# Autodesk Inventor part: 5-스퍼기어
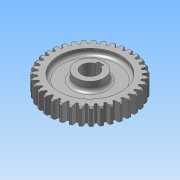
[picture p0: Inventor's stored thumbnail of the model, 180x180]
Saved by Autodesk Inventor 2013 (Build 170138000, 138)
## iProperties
Created: 2013-08
Part Number: 5-스퍼기어
Material: 강
Document SubType Name: Modeling
Designer: 한국산업디자인학원
Categories: <?xml version="1.0" encoding="UTF-16"?> <MemberInstance><Categories><FamilyTemplate><FamilyTemplateParameter ValueType="xs:double" Id="1" ObjectReferenceKey="da
Density: 1 g/cm^3
CustomPartVersion: 1
Author: 한국산업디자인학원
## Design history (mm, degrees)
sketch "Sketch1"
  geometry: C1 r 37 at (0, 0)
  constraints: 1 centre point
  dimensions: "d0" = 74 diameter of C1 (= da_da)
extrude "Extrusion1" new body sketch "Sketch1" distance "d1" = 15 (= da_b); taper "d2" = 0 deg
chamfer "모따기1" distance "d49" = 1; stored, may be unused: second distance "d50" = 2, angle "d51" = 45 deg
workplane "Work Plane2"
feature "피치 지름" dims "d4" = 10, "d5" = 0
workplane "Work Plane8"
workplane "Work Plane9"
feature "스퍼 기어" dims "da_b" = 15, "da_d" = 70, "da_aw" = 70, "da_da" = 74, "da_df" = 65, "da_dw" = 70, angle "da_beta" = 0 deg, "da_lefttooth" = 0, "da_righttooth" = 0
node "작업 평면11"
sketch "스케치3"
  geometry: C1 r 12.5 at (0, 0); 1 further point
  constraints: 1 centre point, 1 coincident
  dimensions: "d53" = 25 diameter of C1
extrude "돌출2" join sketch "스케치3" distance "d55" = 31; taper "d56" = 0 deg
sketch "스케치4"
  geometry: L1 (-2.5, 7.071)-(-2.5, 9.8); L2 (-2.5, 9.8)-(2.5, 9.8); L3 (2.5, 9.8)-(2.5, 7.071); C1 r 12.5 at (0, 0) reference; A1 r 7.5 centre (0, 0) between (-2.5, 7.071) and (2.5, 7.071); 1 further point
  constraints: 6 end point, 2 parallel, 2 point on circle, 1 centre point, 1 coincident, 1 midpoint, 1 perpendicular, 1 vertical, 1 vertical alignment
  dimensions: "d57" = 15 diameter of A1; "d59" = 5 distance of L1.end L2.end; "d60" = 17.3 dimension on A1 L2
extrude "돌출3" cut sketch "스케치4" stored distance "d61" = 31; taper "d62" = 0 deg
sketch "스케치5"
  geometry: C1 r 12.5 at (0, 0) reference; C2 r 27.5 at (0, 0); A1 r 36 centre (0, 0) between (-5.215, 35.62) and (-7.633, 35.181) reference
  constraints: 1 centre point, 1 coincident
  dimensions: "d63" = 55 diameter of C2
extrude "돌출4" cut sketch "스케치5" distance "d65" = 5; taper "d66" = 0 deg
sketch "스케치6"
  geometry: C1 r 12.5 at (0, 0) reference; C2 r 27.5 at (0, 0); A1 r 32.5 centre (0, 0) between (9.347, 31.127) and (7.941, 31.515) reference
  constraints: 1 centre point, 1 coincident
  dimensions: "d67" = 55 diameter of C2
extrude "돌출5" cut sketch "스케치6" distance "d69" = 5; taper "d70" = 0 deg
fillet "모깎기2" dims "d72" = 3
fillet "모깎기3" dims "d73" = 3
body "Solid1"
sketch "Sketch2"
  geometry: C1 r 37 at (0, 0) reference; C2 r 35 at (0, 0)
  constraints: 1 centre point, 1 coincident
  dimensions: "d3" = 70 diameter of C2 (= da_dw)
body "Srf1"
other parameters: "d17" = 0, "d34" = 0.8976 (computed from da_z), "d39" = 0, "d41" = 0, "d47" = 0, "d48" = 0, "d52" = 3
